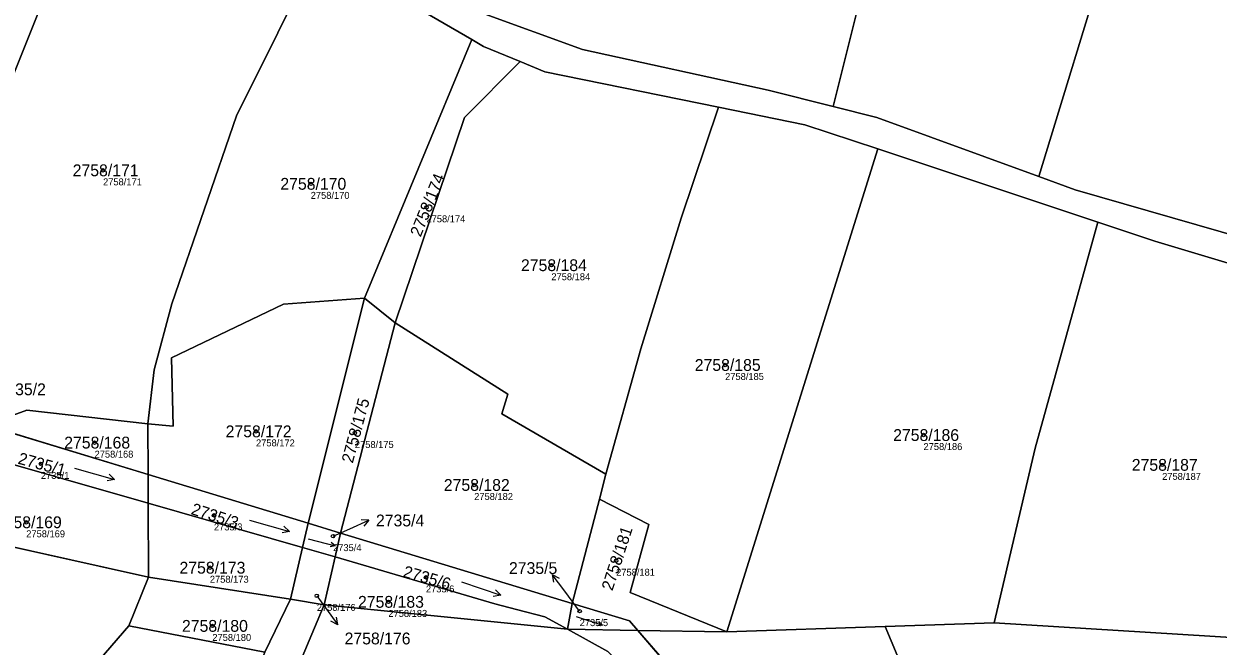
# Model space of a CAD drawing. Extents: x -739214 to -733252, y -1147612 to -1142842.
# Drawn here: x -737857.5 to -737685.7, y -1144384.1 to -1144294.5 of the extents above; entities that cross this region are included whole.
import ezdxf

# ---------------------------------------------------------------- set-up
doc = ezdxf.new("R2010")
doc.units = 0
for name, color, linetype in [('Definiční body', 7, 'Continuous'), ('Hranice parcel', 7, 'Continuous'), ('Parcelní čísla', 7, 'Continuous'), ('Polygon parcely', 7, 'Continuous'), ('Pop  PČ popisy', 7, 'Continuous'), ('Značky kultur', 7, 'Continuous')]:
    doc.layers.add(name, color=color, linetype=linetype)

msp = doc.modelspace()

# ---------------------------------------------------------------- linework, layer by layer
at = {"layer": 'Definiční body'}
for centre in [(-737846.13, -1144315.61), (-737816.26, -1144317.55), (-737799.61, -1144320.93), (-737781.65, -1144329.26), (-737756.66, -1144343.62), (-737824.13, -1144353.17), (-737847.35, -1144354.79), (-737809.91, -1144353.4), (-737728.12, -1144353.7), (-737855.07, -1144357.84), (-737693.8, -1144357.99), (-737792.75, -1144360.88), (-737830.18, -1144365.26), (-737857.18, -1144366.25), (-737813.05, -1144368.24), (-737772.33, -1144371.78), (-737830.77, -1144372.79), (-737799.69, -1144374.18), (-737815.38, -1144376.84), (-737805.09, -1144377.7), (-737777.58, -1144379.03), (-737830.41, -1144381.16)]:
    msp.add_circle(centre, 0.25, dxfattribs=at)
at = {"layer": 'Hranice parcel'}
for p, q in [((-737808.51, -1144334), (-737793.09, -1144296.79)), ((-737756.43, -1144382.02), (-737734.7, -1144312.53)), ((-737734.7, -1144312.53), (-737703.04, -1144323.08)), ((-737816.63, -1144366.38), (-737808.51, -1144334)), ((-737808.51, -1144334), (-737804.11, -1144337.55)), ((-737811.97, -1144367.8), (-737804.11, -1144337.55)), ((-737839.66, -1144359.37), (-737863.03, -1144352.26)), ((-737839.66, -1144359.37), (-737839.69, -1144352.09)), ((-737839.65, -1144363.51), (-737839.66, -1144359.37)), ((-737816.63, -1144366.38), (-737839.66, -1144359.37)), ((-737774.74, -1144362.91), (-737773.81, -1144359.33)), ((-737774.74, -1144362.91), (-737778.64, -1144377.93)), ((-737839.65, -1144363.51), (-737817.44, -1144369.87)), ((-737839.61, -1144374.13), (-737839.65, -1144363.51)), ((-737873.57, -1144366.58), (-737839.61, -1144374.13)), ((-737817.44, -1144369.87), (-737816.63, -1144366.38)), ((-737811.97, -1144367.8), (-737816.63, -1144366.38)), ((-737812.75, -1144371.21), (-737811.97, -1144367.8)), ((-737778.64, -1144377.93), (-737811.97, -1144367.8)), ((-737819.16, -1144377.29), (-737817.44, -1144369.87)), ((-737817.44, -1144369.87), (-737812.75, -1144371.21)), ((-737814.34, -1144378.15), (-737812.75, -1144371.21)), ((-737842.4, -1144381.17), (-737839.61, -1144374.13)), ((-737839.61, -1144374.13), (-737819.16, -1144377.29)), ((-737819.16, -1144377.29), (-737822.86, -1144384.96)), ((-737819.16, -1144377.29), (-737814.34, -1144378.15)), ((-737817.51, -1144385.68), (-737814.34, -1144378.15)), ((-737814.34, -1144378.15), (-737779.31, -1144381.64)), ((-737778.64, -1144377.93), (-737779.31, -1144381.64)), ((-737855.23, -1144395.98), (-737842.4, -1144381.17)), ((-737822.86, -1144384.96), (-737842.4, -1144381.17)), ((-737779.31, -1144381.64), (-737769.21, -1144381.81)), ((-737760.41, -1144392.01), (-737769.21, -1144381.81)), ((-737769.21, -1144381.81), (-737756.43, -1144382.02)), ((-737756.43, -1144382.02), (-737733.64, -1144381.24)), ((-737733.64, -1144381.24), (-737717.97, -1144380.71)), ((-737733.64, -1144381.24), (-737728.72, -1144393.06)), ((-737717.97, -1144380.71), (-737682.31, -1144382.93))]:
    msp.add_line(p, q, dxfattribs=at)
for points in [[(-737696.15, -1144179.54), (-737702.56, -1144192.49), (-737718.72, -1144233.73), (-737727.76, -1144259.01), (-737735.31, -1144283.15), (-737741.14, -1144306.42)], [(-737664.66, -1144198.21), (-737677.91, -1144222.33), (-737683.48, -1144234.43), (-737693.14, -1144259.41), (-737701.4, -1144283.34), (-737711.53, -1144316.51)], [(-737871.43, -1144355.33), (-737865.25, -1144324.99), (-737858.85, -1144301.49), (-737853.3, -1144287.51), (-737842.97, -1144265.49)], [(-737815.04, -1144283.81), (-737826.96, -1144307.78), (-737836.22, -1144334.8), (-737838.79, -1144344.3), (-737839.69, -1144352.09)], [(-737815.04, -1144283.81), (-737811.74, -1144285.96), (-737793.09, -1144296.79)], [(-737741.14, -1144306.42), (-737750.46, -1144304.05), (-737777.16, -1144298.24), (-737791.71, -1144292.95)], [(-737793.09, -1144296.79), (-737791.41, -1144297.77), (-737786.16, -1144299.94)], [(-737804.11, -1144337.55), (-737794.16, -1144307.99), (-737786.16, -1144299.94)], [(-737786.16, -1144299.94), (-737782.58, -1144301.42), (-737757.63, -1144306.5)], [(-737773.81, -1144359.33), (-737768.77, -1144341.3), (-737762.97, -1144322.51), (-737757.63, -1144306.5)], [(-737757.63, -1144306.5), (-737745.18, -1144309.04), (-737734.7, -1144312.53)], [(-737711.53, -1144316.51), (-737734.84, -1144308.02), (-737741.14, -1144306.42)], [(-737678.3, -1144326.45), (-737706.31, -1144318.41), (-737711.53, -1144316.51)], [(-737717.97, -1144380.71), (-737712.05, -1144355.59), (-737703.04, -1144323.08)], [(-737703.04, -1144323.08), (-737694.83, -1144325.82), (-737668.97, -1144333.59)], [(-737839.69, -1144352.09), (-737836.04, -1144352.41), (-737836.31, -1144342.58), (-737820.2, -1144334.87), (-737808.51, -1144334)], [(-737773.81, -1144359.33), (-737788.79, -1144350.64), (-737787.93, -1144347.8), (-737804.11, -1144337.55)], [(-737839.69, -1144352.09), (-737857.1, -1144350.1), (-737863.03, -1144352.26)], [(-737865.02, -1144352.99), (-737866.16, -1144355.92), (-737839.65, -1144363.51)], [(-737756.43, -1144382.02), (-737770.31, -1144376.36), (-737767.63, -1144366.57), (-737774.74, -1144362.91)], [(-737812.75, -1144371.21), (-737789.76, -1144377.99), (-737786.68, -1144378.82), (-737782.59, -1144379.84), (-737779.31, -1144381.64)], [(-737769.21, -1144381.81), (-737770.39, -1144380.44), (-737778.64, -1144377.93)], [(-737779.31, -1144381.64), (-737773.51, -1144384.84), (-737766.78, -1144391.31), (-737766.39, -1144391.81)]]:
    msp.add_lwpolyline(points, dxfattribs=at)
at = {"layer": 'Polygon parcely'}
for points in [[(-737736.94, -1144154.13), (-737743.89, -1144148.46), (-737756.47, -1144176.32), (-737774.04, -1144228.79), (-737783.15, -1144260.28), (-737791.71, -1144292.95), (-737777.16, -1144298.24), (-737750.46, -1144304.05), (-737741.14, -1144306.42), (-737735.31, -1144283.15), (-737727.76, -1144259.01), (-737718.72, -1144233.73), (-737702.56, -1144192.49), (-737696.15, -1144179.54), (-737715.96, -1144172.28)], [(-737718.72, -1144233.73), (-737727.76, -1144259.01), (-737735.31, -1144283.15), (-737741.14, -1144306.42), (-737734.84, -1144308.02), (-737711.53, -1144316.51), (-737701.4, -1144283.34), (-737693.14, -1144259.41), (-737683.48, -1144234.43), (-737677.91, -1144222.33), (-737664.66, -1144198.21), (-737696.15, -1144179.54), (-737702.56, -1144192.49)], [(-737693.14, -1144259.41), (-737701.4, -1144283.34), (-737711.53, -1144316.51), (-737706.31, -1144318.41), (-737678.3, -1144326.45), (-737671.44, -1144301.9), (-737661.73, -1144274.24), (-737655.93, -1144258.59), (-737646.3, -1144234.83), (-737637.16, -1144218.23), (-737648.71, -1144206.53), (-737660.98, -1144196.62), (-737664.66, -1144198.21), (-737677.91, -1144222.33), (-737683.48, -1144234.43)], [(-737858.85, -1144301.49), (-737853.3, -1144287.51), (-737842.97, -1144265.49), (-737868.38, -1144246.05), (-737886.17, -1144233), (-737904.16, -1144222.53), (-737922.96, -1144213.72), (-737924.47, -1144213.16), (-737933.97, -1144244.83), (-737940.49, -1144276.94), (-737944.95, -1144302.96), (-737952.35, -1144361.12), (-737914.15, -1144364.19), (-737873.57, -1144366.58), (-737871.43, -1144355.33), (-737865.25, -1144324.99)], [(-737815.04, -1144283.81), (-737841.56, -1144266.57), (-737842.97, -1144265.49), (-737853.3, -1144287.51), (-737858.85, -1144301.49), (-737865.25, -1144324.99), (-737871.43, -1144355.33), (-737865.02, -1144352.99), (-737864.56, -1144351.8), (-737863.03, -1144352.26), (-737857.1, -1144350.1), (-737839.69, -1144352.09), (-737838.79, -1144344.3), (-737836.22, -1144334.8), (-737826.96, -1144307.78)], [(-737836.31, -1144342.58), (-737820.2, -1144334.87), (-737808.51, -1144334), (-737793.09, -1144296.79), (-737811.74, -1144285.96), (-737815.04, -1144283.81), (-737826.96, -1144307.78), (-737836.22, -1144334.8), (-737838.79, -1144344.3), (-737839.69, -1144352.09), (-737836.04, -1144352.41)], [(-737804.11, -1144337.55), (-737794.16, -1144307.99), (-737786.16, -1144299.94), (-737791.41, -1144297.77), (-737793.09, -1144296.79), (-737808.51, -1144334)], [(-737768.77, -1144341.3), (-737762.97, -1144322.51), (-737757.63, -1144306.5), (-737782.58, -1144301.42), (-737786.16, -1144299.94), (-737794.16, -1144307.99), (-737804.11, -1144337.55), (-737787.93, -1144347.8), (-737788.79, -1144350.64), (-737773.81, -1144359.33)], [(-737734.7, -1144312.53), (-737745.18, -1144309.04), (-737757.63, -1144306.5), (-737762.97, -1144322.51), (-737768.77, -1144341.3), (-737773.81, -1144359.33), (-737774.74, -1144362.91), (-737767.63, -1144366.57), (-737770.31, -1144376.36), (-737756.43, -1144382.02)], [(-737717.97, -1144380.71), (-737712.05, -1144355.59), (-737703.04, -1144323.08), (-737734.7, -1144312.53), (-737756.43, -1144382.02), (-737733.64, -1144381.24)], [(-737675.88, -1144357.27), (-737668.97, -1144333.59), (-737694.83, -1144325.82), (-737703.04, -1144323.08), (-737712.05, -1144355.59), (-737717.97, -1144380.71), (-737682.31, -1144382.93)], [(-737816.63, -1144366.38), (-737808.51, -1144334), (-737820.2, -1144334.87), (-737836.31, -1144342.58), (-737836.04, -1144352.41), (-737839.69, -1144352.09), (-737839.66, -1144359.37)], [(-737811.97, -1144367.8), (-737804.11, -1144337.55), (-737808.51, -1144334), (-737816.63, -1144366.38)], [(-737787.93, -1144347.8), (-737804.11, -1144337.55), (-737811.97, -1144367.8), (-737778.64, -1144377.93), (-737774.74, -1144362.91), (-737773.81, -1144359.33), (-737788.79, -1144350.64)], [(-737839.69, -1144352.09), (-737857.1, -1144350.1), (-737863.03, -1144352.26), (-737839.66, -1144359.37)], [(-737839.65, -1144363.51), (-737866.16, -1144355.92), (-737865.02, -1144352.99), (-737871.43, -1144355.33), (-737873.57, -1144366.58), (-737839.61, -1144374.13)], [(-737839.65, -1144363.51), (-737839.66, -1144359.37), (-737863.03, -1144352.26), (-737865.02, -1144352.99), (-737866.16, -1144355.92)], [(-737817.44, -1144369.87), (-737816.63, -1144366.38), (-737839.66, -1144359.37), (-737839.65, -1144363.51)], [(-737767.63, -1144366.57), (-737774.74, -1144362.91), (-737778.64, -1144377.93), (-737770.39, -1144380.44), (-737769.21, -1144381.81), (-737756.43, -1144382.02), (-737770.31, -1144376.36)], [(-737819.16, -1144377.29), (-737817.44, -1144369.87), (-737839.65, -1144363.51), (-737839.61, -1144374.13)], [(-737812.75, -1144371.21), (-737811.97, -1144367.8), (-737816.63, -1144366.38), (-737817.44, -1144369.87)], [(-737782.59, -1144379.84), (-737779.31, -1144381.64), (-737778.64, -1144377.93), (-737811.97, -1144367.8), (-737812.75, -1144371.21), (-737789.76, -1144377.99), (-737786.68, -1144378.82)], [(-737814.34, -1144378.15), (-737812.75, -1144371.21), (-737817.44, -1144369.87), (-737819.16, -1144377.29)], [(-737779.31, -1144381.64), (-737782.59, -1144379.84), (-737786.68, -1144378.82), (-737789.76, -1144377.99), (-737812.75, -1144371.21), (-737814.34, -1144378.15)], [(-737819.16, -1144377.29), (-737839.61, -1144374.13), (-737842.4, -1144381.17), (-737822.86, -1144384.96)], [(-737814.34, -1144378.15), (-737819.16, -1144377.29), (-737822.86, -1144384.96), (-737828.63, -1144400.28), (-737823.9, -1144400.88), (-737817.51, -1144385.68)], [(-737766.39, -1144391.81), (-737766.78, -1144391.31), (-737773.51, -1144384.84), (-737779.31, -1144381.64), (-737814.34, -1144378.15), (-737817.51, -1144385.68), (-737802.29, -1144388.83), (-737781.29, -1144390.88), (-737767.52, -1144391.77)], [(-737770.39, -1144380.44), (-737778.64, -1144377.93), (-737779.31, -1144381.64), (-737769.21, -1144381.81)], [(-737822.86, -1144384.96), (-737842.4, -1144381.17), (-737855.23, -1144395.98), (-737828.63, -1144400.28)], [(-737766.78, -1144391.31), (-737766.39, -1144391.81), (-737760.41, -1144392.01), (-737769.21, -1144381.81), (-737779.31, -1144381.64), (-737773.51, -1144384.84)], [(-737769.21, -1144381.81), (-737760.41, -1144392.01), (-737728.72, -1144393.06), (-737733.64, -1144381.24), (-737756.43, -1144382.02)], [(-737644.37, -1144397.73), (-737563.33, -1144405.98), (-737533.61, -1144409.53), (-737522.36, -1144411.87), (-737539.01, -1144399.35), (-737578.1, -1144394.75), (-737595.96, -1144391.65), (-737628.78, -1144388.05), (-737682.31, -1144382.93), (-737717.97, -1144380.71), (-737733.64, -1144381.24), (-737728.72, -1144393.06), (-737671.96, -1144395.77)]]:
    msp.add_lwpolyline(points, close=True, dxfattribs=at)
for points in [[(-737678.3, -1144326.45), (-737706.31, -1144318.41), (-737711.53, -1144316.51), (-737734.84, -1144308.02), (-737741.14, -1144306.42), (-737750.46, -1144304.05), (-737777.16, -1144298.24), (-737791.71, -1144292.95), (-737809.7, -1144282.52), (-737823.77, -1144273.2), (-737839.18, -1144262.99), (-737853.81, -1144251.92), (-737864.2, -1144244.07), (-737873.34, -1144237.51), (-737884.05, -1144229.82), (-737903.08, -1144219.03), (-737908.2, -1144216.58), (-737921.64, -1144210.16), (-737938.85, -1144203.13), (-737961.08, -1144197.36)], [(-737960.13, -1144201.71), (-737940.37, -1144207.23), (-737924.47, -1144213.16), (-737922.96, -1144213.72), (-737904.16, -1144222.53), (-737886.17, -1144233), (-737868.38, -1144246.05), (-737842.97, -1144265.49), (-737841.56, -1144266.57), (-737815.04, -1144283.81), (-737811.74, -1144285.96), (-737793.09, -1144296.79), (-737791.41, -1144297.77), (-737786.16, -1144299.94), (-737782.58, -1144301.42), (-737757.63, -1144306.5), (-737745.18, -1144309.04), (-737734.7, -1144312.53), (-737703.04, -1144323.08), (-737694.83, -1144325.82), (-737668.97, -1144333.59)], [(-737966.75, -1144376.24), (-737922.57, -1144381.31), (-737912.63, -1144384.83), (-737860.24, -1144395.01), (-737855.23, -1144395.98), (-737842.4, -1144381.17), (-737839.61, -1144374.13), (-737873.57, -1144366.58), (-737914.15, -1144364.19), (-737952.35, -1144361.12)]]:
    msp.add_lwpolyline(points, dxfattribs=at)
at = {"layer": 'Pop  PČ popisy'}
for p, q in [((-737810.63, -1144367.19), (-737807.89, -1144365.97)), ((-737807.89, -1144365.97), (-737809.01, -1144365.92)), ((-737807.89, -1144365.97), (-737808.6, -1144366.83)), ((-737813.05, -1144368.24), (-737810.63, -1144367.19)), ((-737779.72, -1144376.18), (-737781.53, -1144373.78)), ((-737781.53, -1144373.78), (-737780.52, -1144374.28)), ((-737781.53, -1144373.78), (-737781.32, -1144374.88)), ((-737815.38, -1144376.84), (-737814.14, -1144378.56)), ((-737777.58, -1144379.03), (-737779.72, -1144376.18)), ((-737814.14, -1144378.56), (-737812.38, -1144380.99)), ((-737812.38, -1144380.99), (-737813.37, -1144380.47)), ((-737812.38, -1144380.99), (-737812.56, -1144379.88))]:
    msp.add_line(p, q, dxfattribs=at)
at = {"layer": 'Značky kultur'}
for p, q in [((-737850.24, -1144358.45), (-737844.47, -1144360.1)), ((-737844.47, -1144360.1), (-737845.27, -1144359.35)), ((-737844.47, -1144360.1), (-737845.55, -1144360.31)), ((-737825.08, -1144365.93), (-737819.31, -1144367.58)), ((-737819.31, -1144367.58), (-737820.39, -1144367.79)), ((-737819.31, -1144367.58), (-737820.11, -1144366.83)), ((-737816.64, -1144368.61), (-737812.76, -1144369.65)), ((-737812.76, -1144369.65), (-737813.48, -1144369.8)), ((-737812.76, -1144369.65), (-737813.3, -1144369.16)), ((-737794.58, -1144374.8), (-737788.91, -1144376.75)), ((-737788.91, -1144376.75), (-737790, -1144376.91)), ((-737788.91, -1144376.75), (-737789.67, -1144375.96)), ((-737778.1, -1144379.8), (-737774.28, -1144381.04)), ((-737774.28, -1144381.04), (-737775.01, -1144381.16)), ((-737774.28, -1144381.04), (-737774.8, -1144380.52))]:
    msp.add_line(p, q, dxfattribs=at)

# ---------------------------------------------------------------- texts
at = {"layer": 'Definiční body'}
for s, p in [('2758/171', (-737846.13, -1144317.77)), ('2758/170', (-737816.26, -1144319.71)), ('2758/174', (-737799.61, -1144323.09)), ('2758/184', (-737781.65, -1144331.42)), ('2758/185', (-737756.66, -1144345.78)), ('2758/172', (-737824.13, -1144355.33)), ('2758/175', (-737809.91, -1144355.56)), ('2758/168', (-737847.35, -1144356.95)), ('2758/186', (-737728.12, -1144355.86)), ('2735/1', (-737855.07, -1144360)), ('2758/187', (-737693.8, -1144360.15)), ('2758/182', (-737792.75, -1144363.04)), ('2735/3', (-737830.18, -1144367.42)), ('2758/169', (-737857.18, -1144368.41)), ('2735/4', (-737813.05, -1144370.4)), ('2758/181', (-737772.33, -1144373.94)), ('2758/173', (-737830.77, -1144374.95)), ('2735/6', (-737799.69, -1144376.34)), ('2758/176', (-737815.38, -1144379)), ('2758/183', (-737805.09, -1144379.86)), ('2735/5', (-737777.58, -1144381.19)), ('2758/180', (-737830.41, -1144383.32))]:
    msp.add_text(s, height=1, dxfattribs=at).set_placement(p)
at = {"layer": 'Parcelní čísla'}
for s, p in [('2758/171', (-737850.5, -1144316.46)), ('2758/170', (-737820.63, -1144318.4)), ('2758/184', (-737786.02, -1144330.11)), ('2758/185', (-737761.03, -1144344.47)), ('2735/2', (-737861.31, -1144347.97)), ('2758/172', (-737828.5, -1144354.02)), ('2758/186', (-737732.49, -1144354.55)), ('2758/168', (-737851.72, -1144355.64)), ('2758/187', (-737698.17, -1144358.84)), ('2758/182', (-737797.12, -1144361.73)), ('2758/169', (-737861.55, -1144367.1)), ('2735/4', (-737806.88, -1144366.84)), ('2758/173', (-737835.14, -1144373.64)), ('2735/5', (-737787.75, -1144373.69)), ('2758/183', (-737809.46, -1144378.55)), ('2758/180', (-737834.78, -1144382.01)), ('2758/176', (-737811.39, -1144383.82))]:
    msp.add_text(s, height=1.7, dxfattribs=at).set_placement(p)
for s, rotation, p in [('2758/174', 68, (-737800.46, -1144325.3)), ('2758/175', 75, (-737810.22, -1144357.84)), ('2735/1', 345, (-737858.48, -1144357.8)), ('2735/3', 342, (-737833.59, -1144365.05)), ('2758/181', 72, (-737772.87, -1144376.2)), ('2735/6', 344, (-737803.1, -1144374.08))]:
    msp.add_text(s, height=1.7, rotation=rotation, dxfattribs=at).set_placement(p)

doc.saveas('drawing.dxf')
